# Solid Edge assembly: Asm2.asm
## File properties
Author: Sarvanan
Template: sync ansi assembly.asm
Last saved by: Cadcim
Revision: 7
Application: Solid Edge
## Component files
end plate.par
disk.par
support pin.par
spacer.par
center pin.par
bolt.par
nut.par
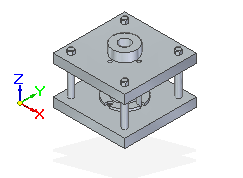
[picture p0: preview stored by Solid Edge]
